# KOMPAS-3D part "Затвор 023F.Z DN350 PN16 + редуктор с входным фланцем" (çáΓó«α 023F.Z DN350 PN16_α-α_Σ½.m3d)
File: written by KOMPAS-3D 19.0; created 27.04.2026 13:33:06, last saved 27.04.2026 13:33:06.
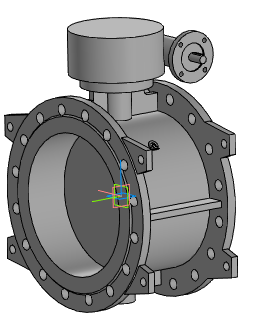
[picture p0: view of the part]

Document properties: Полное имя файла: ..\..\Затвор 023F.Z DN200-DN1600_редуктор с входным фланцем\Затвор 023F.Z DN350 PN16 + редуктор с входным фланцем.a3d

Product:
- Part/product: Затвор 023F.Z DN350 PN16 + редуктор с входным фланцем
    Масса: 166.965

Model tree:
1. Операция без истории:1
